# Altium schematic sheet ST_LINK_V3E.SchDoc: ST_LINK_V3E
size A3; Date: Not used; ApprovedBy: Not used; CheckedBy: Not used; Author: Not used; CompanyName: STMicroelectronics; DrawnBy: Not used; Engineer: Not used; Organization: Not used; Address1: Not used; Address2: Not used; Address3: Not used; Address4: Not used; DocumentNumber: 15; Revision: Not used; SheetNumber: 15; SheetTotal: 16
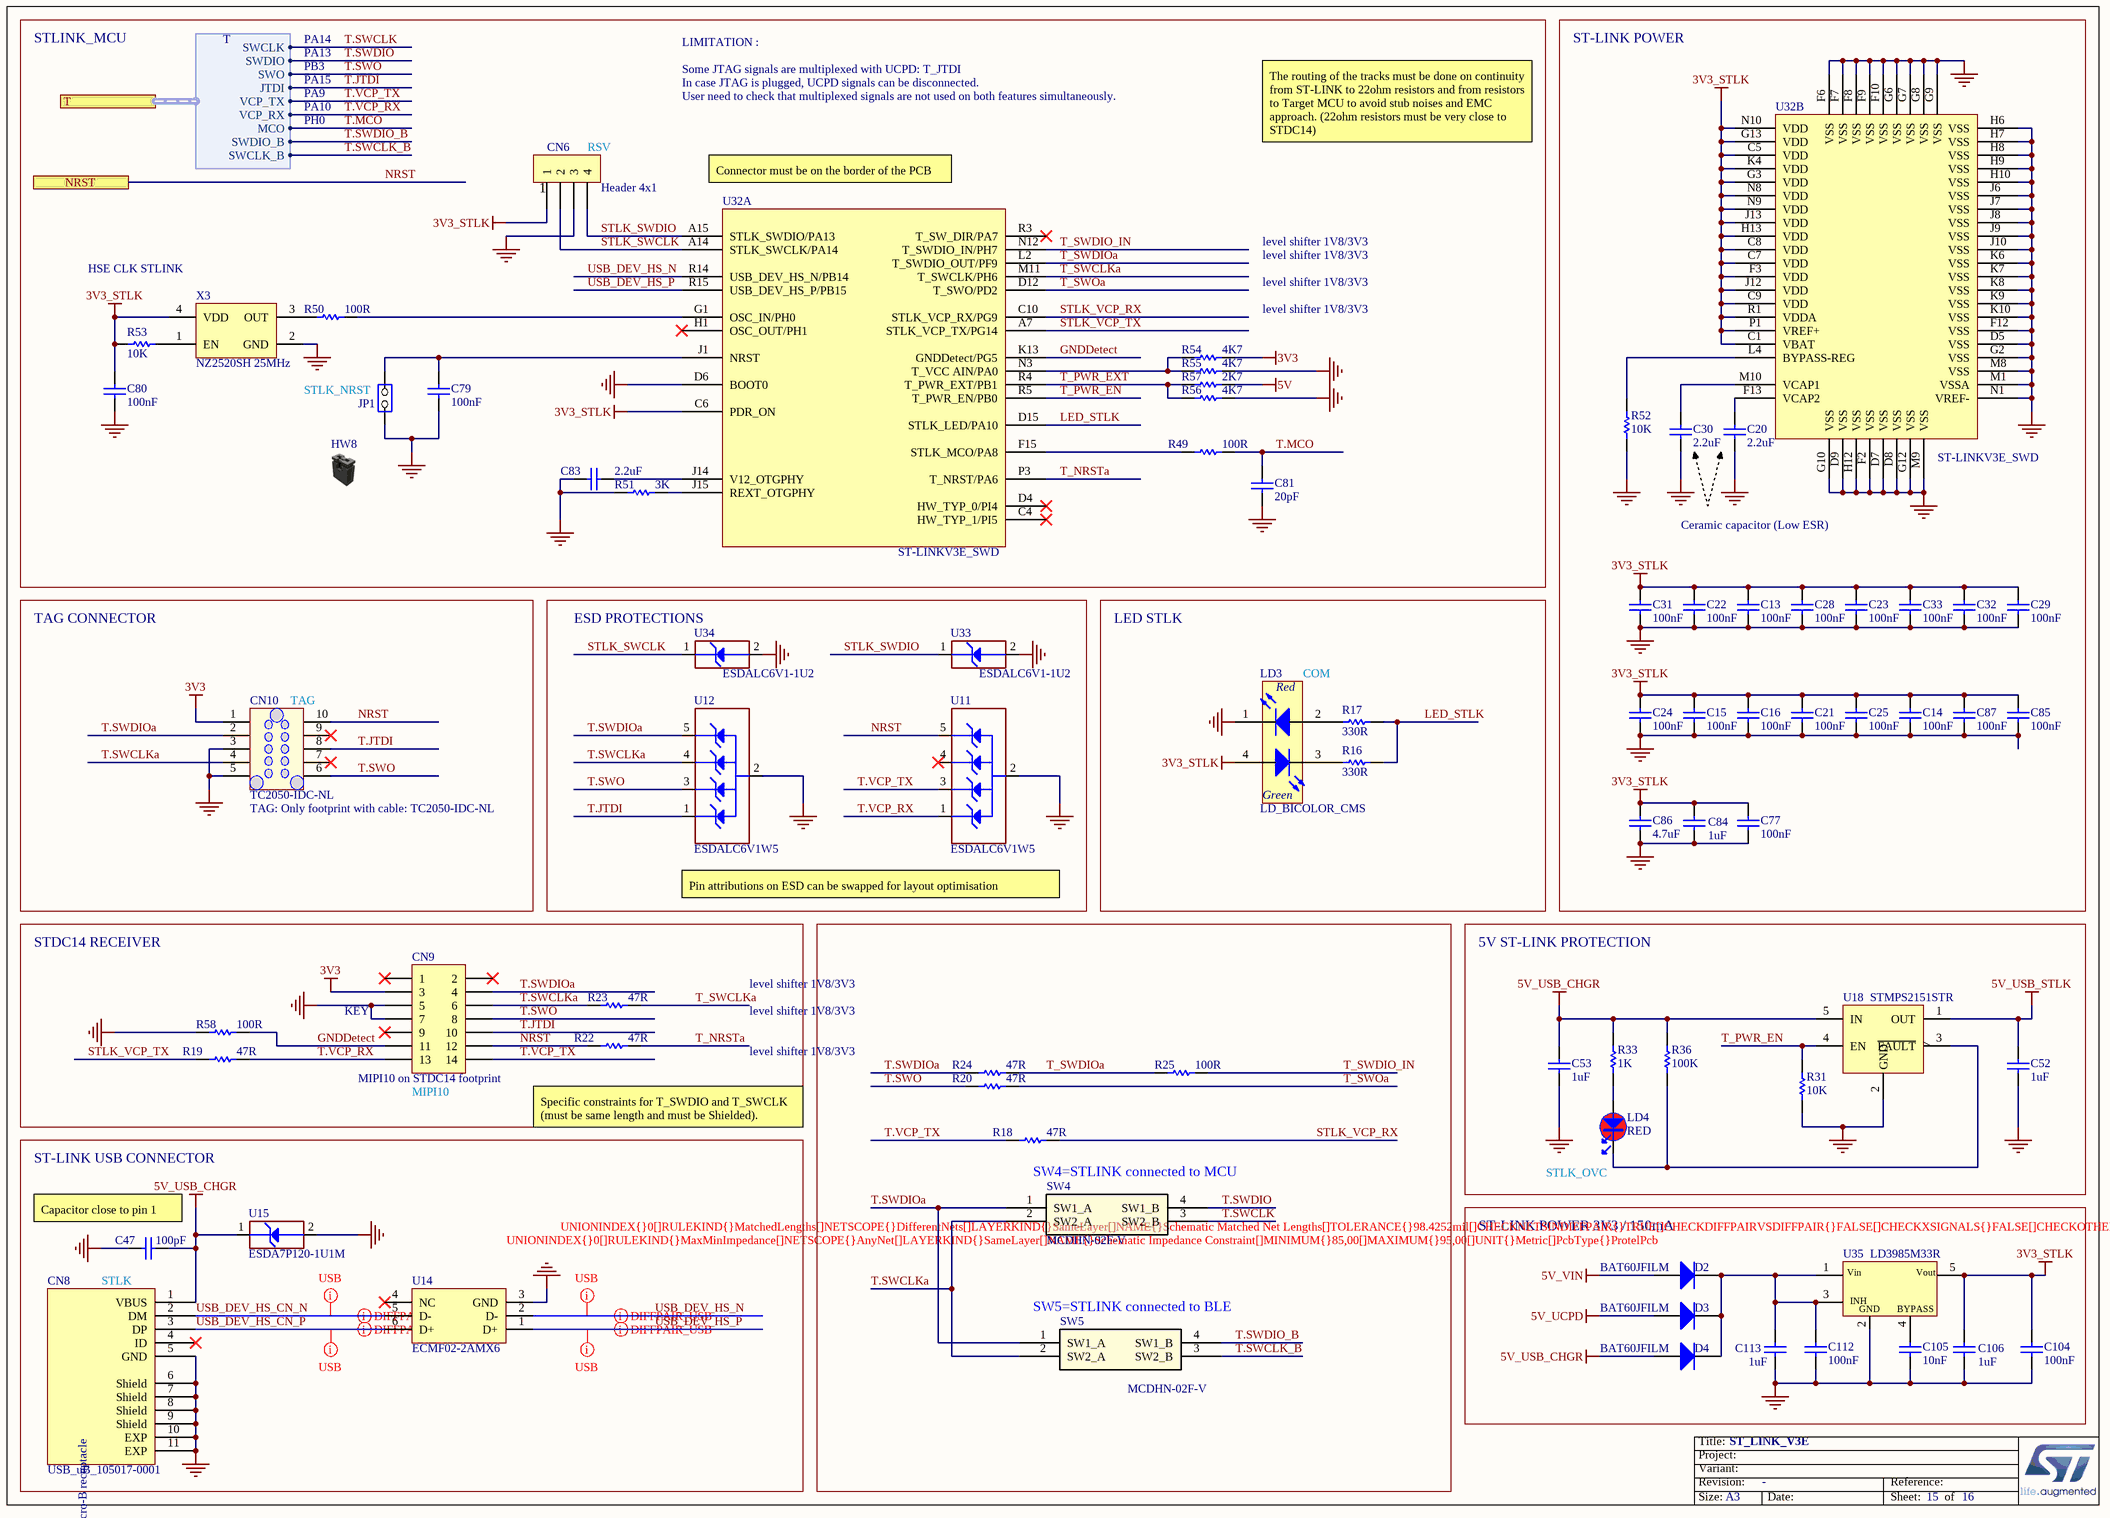
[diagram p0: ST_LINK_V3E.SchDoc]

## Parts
C13  value 100nF  [C0402]  (hidden comment: Capacitor)
C14  value 100nF  [C0402]  (hidden comment: Capacitor)
C15  value 100nF  [C0402]  (hidden comment: Capacitor)
C16  value 100nF  [C0402]  (hidden comment: Capacitor)
C20  value 2.2uF  [C0603]  (hidden comment: Capacitor)
C21  value 100nF  [C0402]  (hidden comment: Capacitor)
C22  value 100nF  [C0402]  (hidden comment: Capacitor)
C23  value 100nF  [C0402]  (hidden comment: Capacitor)
C24  value 100nF  [C0402]  (hidden comment: Capacitor)
C25  value 100nF  [C0402]  (hidden comment: Capacitor)
C28  value 100nF  [C0402]  (hidden comment: Capacitor)
C29  value 100nF  [C0402]  (hidden comment: Capacitor)
C30  value 2.2uF  [C0603]  (hidden comment: Capacitor)
C31  value 100nF  [C0402]  (hidden comment: Capacitor)
C32  value 100nF  [C0402]  (hidden comment: Capacitor)
C33  value 100nF  [C0402]  (hidden comment: Capacitor)
C47  value 100pF  [C0402]  (hidden comment: Capacitor)
C52  value 1uF  [C0603]  (hidden comment: Capacitor)
C53  value 1uF  [C0603]  (hidden comment: Capacitor)
C77  value 100nF  [C0402]  (hidden comment: Capacitor)
C79  value 100nF  [C0402]  (hidden comment: Capacitor)
C80  value 100nF  [C0402]  (hidden comment: Capacitor)
C81  value 20pF  [C0402]  (hidden comment: Capacitor)
C83  value 2.2uF  [C0603]  (hidden comment: Capacitor)
C84  value 1uF  [C0603]  (hidden comment: Capacitor)
C85  value 100nF  [C0402]  (hidden comment: Capacitor)
C86  value 4.7uF  [C0603]  (hidden comment: Capacitor)
C87  value 100nF  [C0402]  (hidden comment: Capacitor)
C104  value 100nF  [C0402]  (hidden comment: Capacitor)
C105  value 10nF  [C0402]  (hidden comment: Capacitor)
C106  value 1uF  [C0603]  (hidden comment: Capacitor)
C112  value 100nF  [C0402]  (hidden comment: Capacitor)
C113  value 1uF  [C0603]  (hidden comment: Capacitor)
CN6  Header 4x1  [CON_SAMTEC_TSW-104-07-G-S]
CN8  value USB_uB_105017-0001  [CON_USBMICROB_MOLEX_105017-0001_H2P90]  (hidden comment: USB_uB_105017.0001)
CN9  value MIPI10 on STDC14 footprint  [CON_STDC14_Receiver_MEDIUM_WITH_MIPI10_3D]  (hidden comment: Header 7x2)
CN10  value TC2050-IDC-NL  [CON_TAG-C_TC2050-IDC-NL]
D2  BAT60JFILM  [DIO_SOD323]
D3  BAT60JFILM  [DIO_SOD323]
D4  BAT60JFILM  [DIO_SOD323]
HW8  Shunt Black 2.54mm  (value not drawn)  (mechanical)
JP1  Jumper_Header 2x1  [CON_SAMTEC_TSW-102-07-G-S]  (value not drawn)
LD3  LD_BICOLOR_CMS  [LED_BI-GR_HSMF-A201-A00J1]
LD4  value RED  [LED_0603_RED]  (hidden comment: LED_red)
R16  value 330R  [R0402]  (hidden comment: Resistor)
R17  value 330R  [R0402]  (hidden comment: Resistor)
R18  value 47R  [R0402]  (hidden comment: Resistor)
R19  value 47R  [R0402]  (hidden comment: Resistor)
R20  value 47R  [R0402]  (hidden comment: Resistor)
R22  value 47R  [R0402]  (hidden comment: Resistor)
R23  value 47R  [R0402]  (hidden comment: Resistor)
R24  value 47R  [R0402]  (hidden comment: Resistor)
R25  value 100R  [R0402]  (hidden comment: Resistor)
R31  value 10K  [R0402]  (hidden comment: Resistor)
R33  value 1K  [R0402]  (hidden comment: Resistor)
R36  value 100K  [R0402]  (hidden comment: Resistor)
R49  value 100R  [R0402]  (hidden comment: Resistor)
R50  value 100R  [R0402]  (hidden comment: Resistor)
R51  value 3K  [R0402]  (hidden comment: Resistor)
R52  value 10K  [R0402]  (hidden comment: Resistor)
R53  value 10K  [R0402]  (hidden comment: Resistor)
R54  value 4K7  [R0402]  (hidden comment: Resistor)
R55  value 4K7  [R0402]  (hidden comment: Resistor)
R56  value 4K7  [R0402]  (hidden comment: Resistor)
R57  value 2K7  [R0402]  (hidden comment: Resistor)
R58  value 100R  [R0402]  (hidden comment: Resistor)
SW4  value MCDHN-02F-V  [SWI_MULTICOMP_MCDHN-02F-V_4P]  (hidden comment: SWITCH_2WAY)
SW5  value MCDHN-02F-V  [SWI_MULTICOMP_MCDHN-02F-V_4P]  (hidden comment: SWITCH_2WAY)
U11  ESDALC6V1W5  [ESD_SOT323-5L]
U12  ESDALC6V1W5  [ESD_SOT323-5L]
U14  ECMF02-2AMX6  [ESD_QFN-6L_1P7X1P5_P050]
U15  value ESDA7P120-1U1M  [ESD_QFN1610_2N_1K_2A]  (hidden comment: ESD-TRANSIL)
U18  STMPS2151STR  [MOS_SOT23-5L]
U32  ST-LINKV3E_SWD  [ICC_UFBGA201_176+25_10X10_P065]  (parts A,B of 2)
U33  value ESDALC6V1-1U2  [ESD_ST0201]  (hidden comment: ESD-TRANSIL)
U34  value ESDALC6V1-1U2  [ESD_ST0201]  (hidden comment: ESD-TRANSIL)
U35  LD3985M33R  [REG_SOT23-5L]
X3  value NZ2520SH 25MHz  [OSC_NDK_NZ2520SB_4P]  (hidden comment: OSCILLATOR_4_PINS)

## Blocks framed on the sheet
ST-LINK POWER: C13-C16 C20-C25 C28-C33 C77 C84-C87 R52 U32
TAG CONNECTOR: CN10
ESD PROTECTIONS: U11 U12 U33 U34
LED STLK: LD3 R16 R17
STDC14 RECEIVER: CN9 R19 R22 R23 R58
5V ST-LINK PROTECTION: C52 C53 LD4 R31 R33 R36 U18
ST-LINK USB CONNECTOR: C47 CN8 U14 U15
ST-LINK POWER 3V3 / 150mA: C104-C106 C112 C113 D2-D4 U35

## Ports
NRST, T (harness T)

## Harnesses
T: SWCLK, SWDIO, SWO, JTDI, VCP_RX, VCP_TX, MCO, SWDIO_B, SWCLK_B

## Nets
3V3: CN9.3 CN10.1 R54.2
3V3_STLK: C13.1 C14.1 C15.1 C16.1 C21.1 C22.1 C23.1 C24.1 C25.1 C28.1 C29.1 C31.1 C32.1 C33.1 C77.1 C80.1 C84.2 C85.1 C86.2 C87.1 C104.2 C106.2 CN6.1 LD3.4(YellowGreen_anode) R53.1 U32.C1(VBAT) U32.C5(VDD) U32.C6(PDR_ON) U32.C7(VDD) U32.C8(VDD) U32.C9(VDD) U32.F3(VDD) U32.G3(VDD) U32.G13(VDD) U32.H13(VDD) U32.J12(VDD) U32.J13(VDD) U32.K4(VDD) U32.N8(VDD) U32.N9(VDD) U32.N10(VDD) U32.P1(VREF+) U32.R1(VDDA) U35.5(Vout) X3.4(VDD)
5V: R57.1
5V_UCPD: D3.1(A)
5V_USB_CHGR: C47.2 C53.2 CN8.1(VBUS) D4.1(A) R33.2 R36.2 U15.1(IO1) U18.5(IN)
5V_USB_STLK: C52.2 U18.1(OUT)
5V_VIN: D2.1(A)
GND: C13.2 C14.2 C15.2 C16.2 C20.1 C21.2 C22.2 C23.2 C24.2 C25.2 C28.2 C29.2 C30.1 C31.2 C32.2 C33.2 C47.1 C52.1 C53.1 C77.2 C79.2 C80.2 C81.2 C83.1 C84.1 C85.2 C86.1 C87.2 C104.1 C105.1 C106.1 C112.1 C113.1 CN6.3 CN8.5(GND) CN8.6(Shield) CN8.7(Shield) CN8.8(Shield) CN8.9(Shield) CN8.10(EXP) CN8.11(EXP) CN9.5 CN9.7 CN10.3 CN10.5 JP1.1(COMMON) LD3.1(RED_cathode) R31.1 R51.1 R52.1 R55.2 R56.1 R58.1 U11.2(GND) U12.2(GND) U14.3(GND) U15.2(GND) U18.2(GND) U32.D5(VSS) U32.D6(BOOT0) U32.D7(VSS) U32.D8(VSS) U32.D9(VSS) U32.F2(VSS) U32.F6(VSS) U32.F7(VSS) U32.F8(VSS) U32.F9(VSS) U32.F10(VSS) U32.F12(VSS) U32.G2(VSS) U32.G6(VSS) U32.G7(VSS) U32.G8(VSS) U32.G9(VSS) U32.G10(VSS) U32.G12(VSS) U32.H6(VSS) U32.H7(VSS) U32.H8(VSS) U32.H9(VSS) U32.H10(VSS) U32.H12(VSS) U32.J6(VSS) U32.J7(VSS) U32.J8(VSS) U32.J9(VSS) U32.J10(VSS) U32.K6(VSS) U32.K7(VSS) U32.K8(VSS) U32.K9(VSS) U32.K10(VSS) U32.M1(VSSA) U32.M8(VSS) U32.M9(VSS) U32.N1(VREF-) U33.2(GND) U34.2(GND) U35.2(GND) X3.2(GND)
GNDDetect: CN9.11 R58.2 U32.K13(GNDDetect/PG5)
LED_STLK: R16.2 R17.2 U32.D15(STLK_LED/PA10)
NRST: CN9.12 CN10.10 R22.1 U11.5(IO4) ; port NRST
STLK_SWCLK: CN6.2 U32.A14(STLK_SWCLK/PA14) U34.1(IO1)
STLK_SWDIO: CN6.4 U32.A15(STLK_SWDIO/PA13) U33.1(IO1)
STLK_VCP_RX: R18.2 U32.C10(STLK_VCP_RX/PG9)
STLK_VCP_TX: R19.1 U32.A7(STLK_VCP_TX/PG14)
T.JTDI: CN9.10 CN10.8 U12.1(IO1) ; port T.JTDI
T.MCO: C81.1 R49.2 ; port T.MCO
T.SWCLK: SW4.3(SW2_B) ; port T.SWCLK
T.SWCLK_B: SW5.3(SW2_B) ; port T.SWCLK_B
T.SWCLKa: CN9.6 CN10.4 R23.1 SW4.2(SW2_A) SW5.2(SW2_A) U12.4(IO3)
T.SWDIO: SW4.4(SW1_B) ; port T.SWDIO
T.SWDIO_B: SW5.4(SW1_B) ; port T.SWDIO_B
T.SWDIOa: CN9.4 CN10.2 R24.1 SW4.1(SW1_A) SW5.1(SW1_A) U12.5(IO4)
T.SWO: CN9.8 CN10.6 R20.1 U12.3(IO2) ; port T.SWO
T.VCP_RX: CN9.13 R19.2 U11.1(IO1) ; port T.VCP_RX
T.VCP_TX: CN9.14 R18.1 U11.3(IO2) ; port T.VCP_TX
T_NRSTa: R22.2 U32.P3(T_NRST/PA6)
T_PWR_EN: R31.2 U18.4(EN) U32.R5(T_PWR_EN/PB0)
T_PWR_EXT: R56.2 R57.2 U32.R4(T_PWR_EXT/PB1)
T_SWCLKa: R23.2 U32.M11(T_SWCLK/PH6)
T_SWDIO_IN: R25.2 U32.N12(T_SWDIO_IN/PH7)
T_SWDIOa: R24.2 R25.1 U32.L2(T_SWDIO_OUT/PF9)
T_SWOa: R20.2 U32.D12(T_SWO/PD2)
USB_DEV_HS_CN_N: CN8.2(DM) U14.5(D-)
USB_DEV_HS_CN_P: CN8.3(DP) U14.6(D+)
USB_DEV_HS_N: U14.2(D-) U32.R14(USB_DEV_HS_N/PB14)
USB_DEV_HS_P: U14.1(D+) U32.R15(USB_DEV_HS_P/PB15)
NetC20_2: C20.2 U32.F13(VCAP2)
NetC30_2: C30.2 U32.M10(VCAP1)
NetC79_1: C79.1 JP1.2(NO) U32.J1(NRST)
NetC83_2: C83.2 U32.J14(V12_OTGPHY)
NetC105_2: C105.2 U35.4(BYPASS)
NetC112_2: C112.2 C113.2 D2.2(K) D3.2(K) D4.2(K) U35.1(Vin) U35.3(CE)
NetLD3_2: LD3.2(Red_anode) R17.1
NetLD3_3: LD3.3(YellowGreen_cathode) R16.1
NetLD4_1: LD4.1 R33.1
NetLD4_2: LD4.2 R36.1 U18.3(~{FAULT})
NetR49_1: R49.1 U32.F15(STLK_MCO/PA8)
NetR50_1: R50.1 X3.3(OUT)
NetR50_2: R50.2 U32.G1(OSC_IN/PH0)
NetR51_2: R51.2 U32.J15(REXT_OTGPHY)
NetR52_2: R52.2 U32.L4(BYPASS-REG)
NetR53_2: R53.2 X3.1(EN)
NetR54_1: R54.1 R55.1 U32.N3(T_VCC_AIN/PA0)

Not connected (* = marked no-connect by the designer): CN8 4(ID)*; CN9 1* 2* 9*; CN10 7* 9*; U11 4(IO3)*; U14 4(NC)*; U32 C4(HW_TYP_1/PI5)* D4(HW_TYP_0/PI4)* H1(OSC_OUT/PH1)* R3(T_SW_DIR/PA7)*

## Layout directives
differential pair; rule Impedance Constraint [Min = 85.00    Max = 95.00    ]: USB_DEV_HS_CN_N, USB_DEV_HS_CN_P, USB_DEV_HS_N, USB_DEV_HS_P
rule Undefined; rule Matched Net Lengths [Tolerance = 2.5mm]; rule Impedance Constraint [Min = 85.00    Max = 95.00    ]: USB_DEV_HS_N
rule Undefined; rule Matched Net Lengths [Tolerance = 0.2mm]; rule Impedance Constraint [Min = 85.00    Max = 95.00    ]: USB_DEV_HS_CN_N, USB_DEV_HS_CN_P, USB_DEV_HS_P

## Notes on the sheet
- STLINK_MCU
- PA14
- PA13
- PB3
- PA15
- PA10
- PA9
- LIMITATION :
  Some JTAG signals are multiplexed with UCPD: T_JTDI
  In case JTAG is plugged, UCPD signals can be disconnected.
  User need to check that multiplexed signals are not used on both features simultaneously.
- PH0
- (near CN6) RSV
- Connector must be on the border of the PCB
- The routing of the tracks must be done on continuity from ST-LINK to 22ohm resistors and from resistors to Target MCU to avoid stub noises and EMC approach. (22ohm resistors must be very close to STDC14)
- (near CN6) 1
- level shifter 1V8/3V3
- HSE CLK STLINK
- (near JP1) STLK_NRST
- Ceramic capacitor (Low ESR)
- (near CN10) TAG
- COM
- (near CN10) TAG: Only footprint with cable: TC2050-IDC-NL
- Pin attributions on ESD can be swapped for layout optimisation
- (near R23) level shifter 1V8/3V3
- (near CN9) KEY
- (near R22) level shifter 1V8/3V3
- (near CN9) MIPI10
- (near R22) Specific constraints for T_SWDIO and T_SWCLK (must be same length and must be Shielded).
- SW4=STLINK connected to MCU
- (near LD4) STLK_OVC
- (near C47) Capacitor close to pin 1
- STLK
- (near SW5) SW5=STLINK connected to BLE

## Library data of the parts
C13-C16 C21-C25 C28 C29 C31-C33 C77 C79 C80 C85 C87 C104 C112 = MCD-00006: Capacitor, MLCC, 100nF, 16V, X7R, 10%, 0402, T=0.5mm; Manufacturer_Part_Number: CC0402KRX7R7BB104; Manufacturer: YAGEO; Provided_By: SUBCO; Initial_Board_Reference: MB1274
C20 C30 = MCD-00012: Capacitor, MLCC, 2.2uF, 10V, X5R, 10%, 0603, T=0,8mm; Manufacturer_Part_Number: CC0603KRX5R6BB225; Manufacturer: YAGEO; Alternate_Manufacturer_Part_Number: C0603C225K8PACTU; Alternate_Manufacturer: KEMET; Provided_By: SUBCO; Initial_Board_Reference: MB1274; Item Type: Item; Path: ws/MCD_ApplicationBoards/Lists/MCDPARTSdatabase
C47 = MCD-00205: Capacitor, MLCC, 100pF, 50V, NPO, 5%, 0402, T=0,5mm; Manufacturer_Part_Number: CC0402JRNPO9BN101; Manufacturer: YAGEO; Provided_By: Subcon; Initial_Board_Reference: MB1361
C52 C53 = MCD-00010: Capacitor, MLCC, 1uF, 16V, X5R, 10%, 0603, T=0,8mm; Manufacturer_Part_Number: CC0603KRX5R7BB105; Manufacturer: YAGEO; Provided_By: SUBCO; Initial_Board_Reference: MB1274; Item Type: Item; Path: ws/MCD_ApplicationBoards/Lists/MCDPARTSdatabase
C81 = MCD-00016: Capacitor, MLCC, 20pF, 50V, NPO, 5%, 0402, T=0,5mm; Manufacturer_Part_Number: CC0402JRNPO9BN200; Manufacturer: YAGEO; Provided_By: Subcon; Initial_Board_Reference: MB1274
C83 = MCD-00012: Capacitor, MLCC, 2.2uF, 10V, X5R, 10%, 0603, T=0,8mm; Manufacturer_Part_Number: CC0603KRX5R6BB225; Manufacturer: YAGEO; Alternate_Manufacturer_Part_Number: C0603C225K8PACTU; Alternate_Manufacturer: KEMET; Provided_By: Subcon; Initial_Board_Reference: MB1274
C84 C106 C113 = MCD-00010: Capacitor, MLCC, 1uF, 16V, X5R, 10%, 0603, T=0,8mm; Manufacturer_Part_Number: CC0603KRX5R7BB105; Manufacturer: YAGEO; Provided_By: Subcon; Initial_Board_Reference: MB1274
C86 = MCD-00009: Capacitor, MLCC, 4.7uF, 16V, X5R, 10%, 0603, T=0.8mm; Manufacturer_Part_Number: CC0603KRX5R7BB475; Manufacturer: YAGEO; Provided_By: subcon; Initial_Board_Reference: MB1274
C105 = MCD-00011: Capacitor, MLCC, 10nF, 16V, X7R, 10%, 0402, T=0.5mm; Manufacturer_Part_Number: CC0402KRX7R7BB103; Manufacturer: YAGEO; Provided_By: Subcon; Initial_Board_Reference: MB1274
CN6 = MCD-00029: Header, 4x1, 2,54mm, VR, TH, Height 5.84mm/2.54mm; Manufacturer_Part_Number: TSW-104-07-x-S; Manufacturer: SAMTEC; Part_Type: Connector; Provided_By: Subcon; Initial_Board_Reference: MB1274
CN8 = MCD-00028: USB-MICRO-B, 0.65mm, RA, SMT, Bottom Mount,; Manufacturer_Part_Number: 1050170001; Manufacturer: MOLEX; Part_Type: Connector; Provided_By: Subcon; Initial_Board_Reference: MB1274
CN9 = MCD-01226: Header 5x2, 1.27mm, Dual row, Straight, Surface mount, vertical male connector. 3.05mm lead. Mates with FFSD connector. Footprint compatible with FTSH-107-01-L-DV,-K,-A,-P,-ES (STDC14 MEDIUM); Manufacturer_Part_Number: FTSH-105-01-L-DV-K; Manufacturer: SAMTEC; Provided_By: Subcon; Initial_Board_Reference: MCD16-052
CN10 = MCD-00031: Tag_Connector Header, 10x2, No legs; Manufacturer_Part_Number: TC2050-IDC-NL-FP; Manufacturer: TAG-CONNECT LLC; Provided_By: Subcon; Initial_Board_Reference: MB1274
D2-D4 = MCD-00034: Manufacturer: STMICROELECTRONICS; Part_Type: Diode; BMS_Part_Number: 9151097; Provided_By: Subcon; Initial_Board_Reference: MB1274
HW8 = MCD-00043: SHUNT 2.54mm BLACK; Manufacturer_Part_Number: SNT-100-BK-G; Manufacturer: SAMTEC; Part_Type: Mechanical; Provided_By: Subcon; Initial_Board_Reference: MB1274
JP1 = MCD-00045: Header, 2x1, 2,54mm, VR, TH, Height 5.84mm/2.54mm; Part_Type: Connector; Manufacturer_Part_Number: TSW-102-07-x-S; Manufacturer: SAMTEC; Value: Shunt not fitted; Provided_By: Subcon; Initial_Board_Reference: MB1274; Remark: 3D KO: BZ: 40098
LD3 = MCD-00051: LED Bicolor; Part_Type: Display; Manufacturer_Part_Number: HSMF-A201-A00J1; Manufacturer: AVAGO TECHNOLOGIES; Alternate_Manufacturer_Part_Number: LE-RGW35280; Alternate_Manufacturer: EVERLUCK; Provided_By: Subcon; Initial_Board_Reference: MB1274
LD4 = MCD-00049: LED, Red, 0603; Manufacturer_Part_Number: 19-213-R6C-AP1Q2B/3T; Manufacturer: EVERLIGHT; Part_Type: Display; Provided_By: Subcon; Initial_Board_Reference: MB1274
R16 R17 = MCD-00062: Resistor,330R,0402,1%,1/16W; Manufacturer_Part_Number: RC0402FR-07330RL; Manufacturer: YAGEO; Provided_By: SUBCO; Initial_Board_Reference: MB1274; Item Type: Item; Path: ws/MCD_ApplicationBoards/Lists/MCDPARTSdatabase
R18-R20 R22-R24 = MCD-00481: Resistor,47R,0402,1%,1/16W; Manufacturer_Part_Number: RC0402FR-0747RL; Manufacturer: YAGEO; Provided_By: SUBCO; Initial_Board_Reference: MBxxxx; Item Type: Item; Path: ws/MCD_ApplicationBoards/Lists/MCDPARTSdatabase
R25 R49 R50 R58 = MCD-00119: Resistor,100R,0402,1%,1/16W; Manufacturer_Part_Number: RC0402FR-07100RL; Manufacturer: YAGEO; Provided_By: Subcon; Initial_Board_Reference: MB1262
R31 = MCD-00053: Resistor,10K,0402,1%,1/16W; Manufacturer_Part_Number: RC0402FR-0710KL; Manufacturer: YAGEO; Provided_By: SUBCO; Initial_Board_Reference: MB1274; Item Type: Item; Path: ws/MCD_ApplicationBoards/Lists/MCDPARTSdatabase
R33 = MCD-00061: Resistor,1K,0402,1%,1/16W; Manufacturer_Part_Number: RC0402FR-071KL; Manufacturer: YAGEO; Provided_By: SUBCO; Initial_Board_Reference: MB1274; Item Type: Item; Path: ws/MCD_ApplicationBoards/Lists/MCDPARTSdatabase
R36 = MCD-00059: Resistor,100K,0402,1%,1/16W; Manufacturer_Part_Number: RC0402FR-07100KL; Manufacturer: YAGEO; Alternate_Manufacturer_Part_Number: RT0402FRE07100KL; Provided_By: SUBCO; Initial_Board_Reference: MB1274; Item Type: Item; Path: ws/MCD_ApplicationBoards/Lists/MCDPARTSdatabase
R51 = MCD-00185: Resistor,3K,0402,1%,1/16W; Manufacturer_Part_Number: RC0402FR-073KL; Manufacturer: YAGEO; Provided_By: Subcon
R52 R53 = MCD-00053: Resistor,10K,0402,1%,1/16W; Manufacturer_Part_Number: RC0402FR-0710KL; Manufacturer: YAGEO; Provided_By: subcon; Initial_Board_Reference: MB1274
R54-R56 = MCD-00065: Resistor,4K7,0402,1%,1/16W; Manufacturer_Part_Number: RC0402FR-074K7L; Manufacturer: YAGEO; Alternate_Manufacturer_Part_Number: RT0402FRE074K7L; Provided_By: Subcon; Initial_Board_Reference: MB1274
R57 = MCD-00055: Resistor,2K7,0402,1%,1/16W; Manufacturer_Part_Number: RC0402FR-072K7L; Manufacturer: YAGEO; Provided_By: Subcon; Initial_Board_Reference: MB1274
SW4 SW5 = MCD-02105: DIP Switch Slide Type x2 poles 25mA 24VDC 100mR SMD; Part_Type: Misc; Manufacturer: MULTICOMP; Provided_By: SUBCO
U11 U12 = MCD-00136: Dual Transil array for ESD protection; Part_Type: Diode; Manufacturer: STMICROELECTRONICS; BMS_Part_Number: 9151112; Provided_By: Subcon; Initial_Board_Reference: MB1262
U14 = MCD-00649: Common mode filter with ESD protection for USB 2.0 interface; Part_Type: Diode; Manufacturer: STMICROELECTRONICS; Provided_By: Subcon; Initial_Board_Reference: MB1248
U15 = MCD-01026: High power transient voltage suppressor; Part_Type: Diode; Manufacturer: STMICROELECTRONICS; Provided_By: SUBCO with ST control; Initial_Board_Reference: MB1378; Remark: Footprint moved fromROU lib: DFN105P160X60-2N to global-lib: ESD_QFN1610_2N_1K_2A; Item Type: Item; Path: ws/MCD_ApplicationBoards/Lists/MCDPARTSdatabase
U18 = MCD-00159: 500mA, Enhanced single channel power switches with active high enable pin; Part_Type: IC; Manufacturer: STMICROELECTRONICS; Alternate_Manufacturer_Part_Number: TPS2051C; Alternate_Manufacturer: TEXAS INSTRUMENTS; BMS_Part_Number: 9159009; Provided_By: Subcon; Initial_Board_Reference: MB1264
U32 = MCD-00596: STM32F723IEK  (STM32F7) BGA176; Part_Type: IC; Manufacturer_Part_Number: STM32F723IEK6; Manufacturer: STMICROELECTRONICS; BMS_Part_Number: 9175300; Provided_By: SUBCO with ST control; Initial_Board_Reference: MB1331; Item Type: Item; Path: ws/MCD_ApplicationBoards/Lists/MCDPARTSdatabase
U33 U34 = MCD-00170: ESD protection 6V1; Part_Type: Diode; Manufacturer: STMICROELECTRONICS; BMS_Part_Number: 9151132; Provided_By: Subcon; Initial_Board_Reference: MB1274
U35 = MCD-00086: Ultra low drop-low noise BiCMOS voltage, regulators low ESR capacitors compatible; Manufacturer: STMICROELECTRONICS; Part_Type: IC; BMS_Part_Number: 9176161; Provided_By: Subcon; Initial_Board_Reference: MB1274
X3 = MCD-00597: Oscillator 25Mhz, +-50ppm, Vcc:3.3V typ, square wave: [0.1Vcc;0.9Vcc], Enable pin, SMD; Part_Type: Crystal_Osc; Manufacturer_Part_Number: NZ2520SH 25MHz END4869C; Manufacturer: NDK; Alternate_Manufacturer_Part_Number: NZ2520SB 25MHz END4869B; BMS_Part_Number: 9157050; Provided_By: SUBCO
